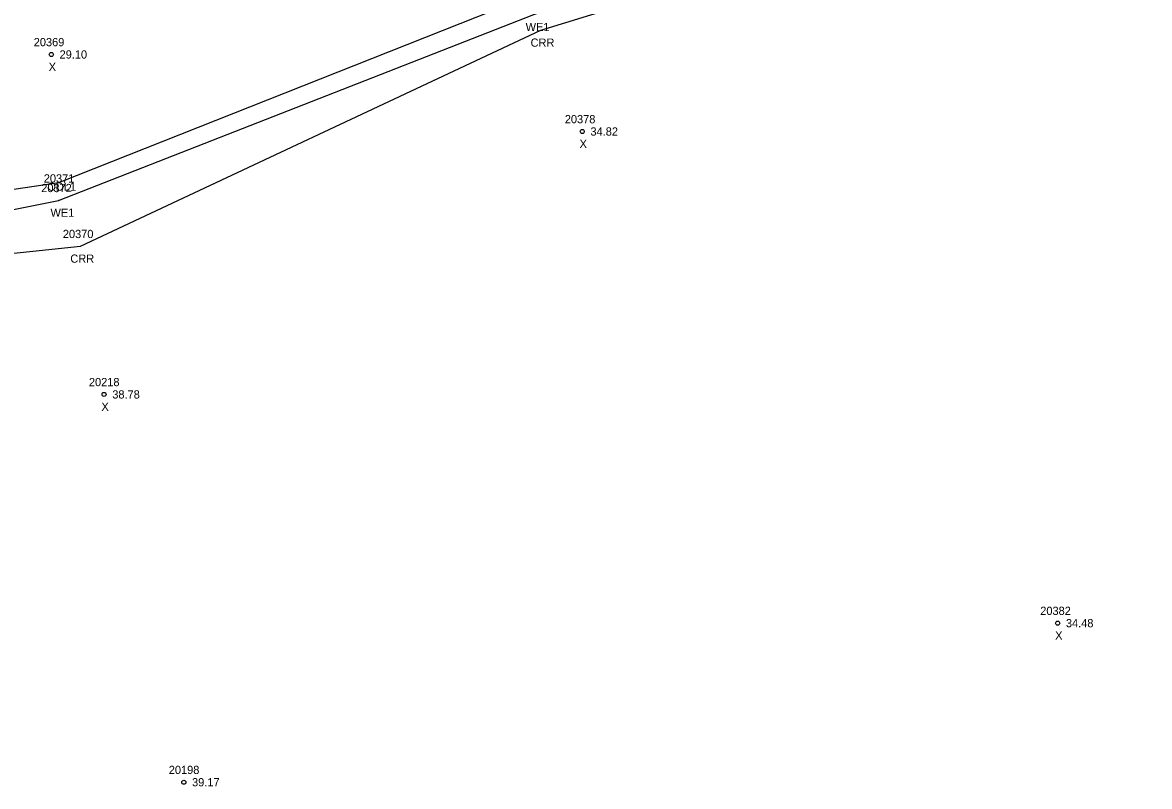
# Model space of a CAD drawing. Extents: x 2445178 to 2446260, y 791158 to 792318.
# Drawn here: x 2445783.8 to 2445920.9, y 791717.2 to 791810 of the extents above; entities that cross this region are included whole.
import ezdxf

# ---------------------------------------------------------------- set-up
doc = ezdxf.new("R2010")
doc.units = 0
for name, color, linetype in [('RD_EX_H2O', 7, 'Continuous'), ('RD_EX_H2O_txCode', 7, 'Continuous'), ('RD_Sketch8', 7, 'Continuous'), ('RD_SMD_Locator', 7, 'Continuous')]:
    doc.layers.add(name, color=color, linetype=linetype)

msp = doc.modelspace()

# ---------------------------------------------------------------- linework, layer by layer
at = {"layer": 'RD_EX_H2O'}
for points in [[(2445752.43, 791785.31), (2445788.27, 791790.61), (2445845.46, 791813.31), (2445889.72, 791828.98), (2445868.44, 791886.37), (2445910.27, 791920.69), (2445939.62, 791931.64), (2445988.31, 791964.33), (2446005.31, 791961.03), (2446034.89, 791932.66), (2446061.86, 791927.42), (2446120.16, 791928.99), (2446131.56, 791958.98), (2446161.23, 791962.03), (2446198.32, 792006.02)], [(2445746.88, 791778.25), (2445790.91, 791782.86), (2445846.87, 791809.11), (2445896.01, 791824.25), (2445877, 791883.78), (2445912.26, 791916.16), (2445942.78, 791927.77), (2445991.6, 791962.06), (2446003.69, 791956.06), (2446036.32, 791927.07), (2446060.96, 791923.67), (2446122.97, 791923.97), (2446134.24, 791956.18), (2446163.21, 791958.01), (2446202.51, 792004.24)], [(2445748.32, 791780.49), (2445788.24, 791788.44), (2445846, 791811.01), (2445891.85, 791826.96), (2445872.2, 791885.31), (2445911.58, 791917.24), (2445942.41, 791930.41), (2445989.95, 791963.2), (2446004.43, 791957.67), (2446037.13, 791928.19), (2446062.94, 791924.63), (2446122.42, 791925.89), (2446133.98, 791956.62), (2446163.05, 791958.48), (2446202.11, 792005.16)]]:
    msp.add_lwpolyline(points, dxfattribs=at)
at = {"layer": 'RD_SMD_Locator'}
for centre, radius in [((2445846.87, 791809.11), 0.001), ((2445787.35, 791806.17), 0.25), ((2445851.9, 791796.81), 0.25), ((2445788.27, 791790.61), 0.001), ((2445788.24, 791788.44), 0.001), ((2445790.91, 791782.86), 0.001), ((2445793.76, 791764.86), 0.25), ((2445909.71, 791737.06), 0.25), ((2445803.46, 791717.73), 0.25)]:
    msp.add_circle(centre, radius, dxfattribs=at)

# ---------------------------------------------------------------- texts
at = {"layer": 'RD_EX_H2O_txCode'}
for s, p in [('WE1', (2445845.02, 791809.01)), ('CRR', (2445845.62, 791807.11)), ('20371', (2445786.43, 791790.61)), ('20372', (2445786.12, 791789.44)), ('ODL1', (2445786.86, 791789.61)), ('WE1', (2445787.25, 791786.44)), ('20370', (2445788.75, 791783.86)), ('CRR', (2445789.66, 791780.86))]:
    msp.add_text(s, height=1, dxfattribs=at).set_placement(p)
at = {"layer": 'RD_Sketch8'}
for s, p in [('20369', (2445785.21, 791807.17)), ('29.10', (2445788.35, 791805.67)), ('X', (2445787.03, 791804.17)), ('20378', (2445849.78, 791797.81)), ('34.82', (2445852.9, 791796.31)), ('X', (2445851.58, 791794.81)), ('20218', (2445791.92, 791765.86)), ('38.78', (2445794.76, 791764.36)), ('X', (2445793.44, 791762.86)), ('20382', (2445907.59, 791738.06)), ('34.48', (2445910.71, 791736.56)), ('X', (2445909.4, 791735.06)), ('20198', (2445801.63, 791718.73)), ('39.17', (2445804.46, 791717.23))]:
    msp.add_text(s, height=1, dxfattribs=at).set_placement(p)

doc.saveas('drawing.dxf')
